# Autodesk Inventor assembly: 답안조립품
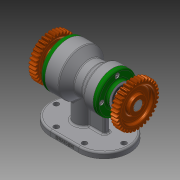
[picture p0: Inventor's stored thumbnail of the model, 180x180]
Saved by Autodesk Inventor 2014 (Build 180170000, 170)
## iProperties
Created: 2020-01
Part Number: 답안조립품
Document SubType Name: Assembly
Designer: kh
Author: kh
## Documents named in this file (13)
- C:\Users\kh\Desktop\700104V1038\답안조립품.iam
- C:\Users\kh\Desktop\700104V1038\본체.ipt
- C:\Users\kh\Desktop\700104V1038\베어링 6203.ipt
- C:\Users\kh\Desktop\700104V1038\베어링 6205.ipt
- C:\Users\kh\Desktop\700104V1038\축.ipt
- C:\Users\kh\Desktop\700104V1038\뒤커버.ipt
- C:\Users\kh\Desktop\700104V1038\앞커버.ipt
- C:\Users\kh\Desktop\700104V1038\오일 실 25 38 8.ipt
- C:\Users\kh\Desktop\700104V1038\오일 실 17 30 8.ipt
- C:\Users\kh\Desktop\700104V1038\볼트 M4.ipt
- C:\Users\kh\Desktop\700104V1038\키 5 x 5 x 18.ipt
- C:\Users\kh\Desktop\700104V1038\스퍼기어.ipt
- C:\Users\kh\Desktop\700104V1038\멈춤나사 M3.ipt
